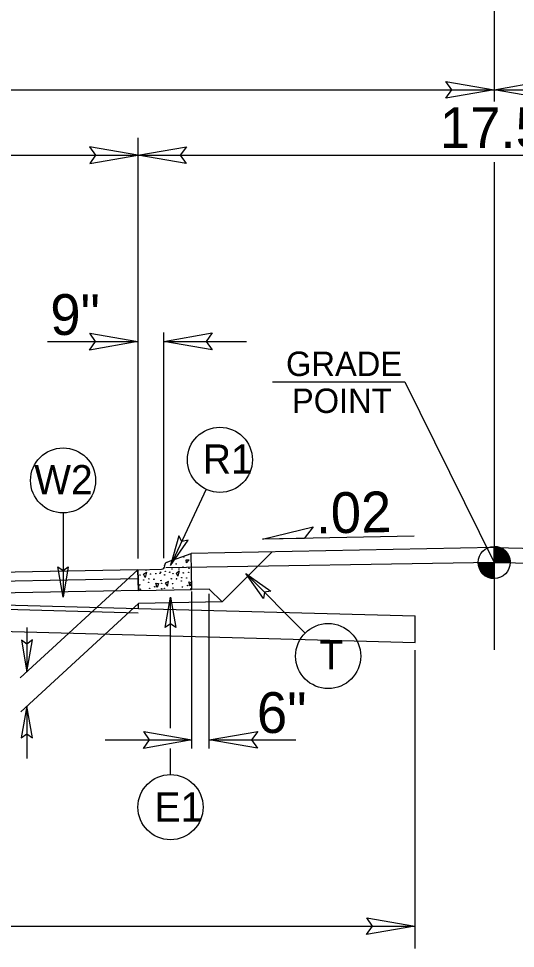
# Model space of a CAD drawing. Extents: x 957297 to 961629, y 830661 to 840840.
# Drawn here: x 959403.5 to 959498.6, y 836659.8 to 836837.7 of the extents above; entities that cross this region are included whole.
import ezdxf

# ---------------------------------------------------------------- set-up
doc = ezdxf.new("R2010")
doc.units = 0
for name, color, linetype in [('Default', 7, 'Continuous'), ('Old_Level_1', 7, 'Continuous'), ('Old_Level_11', 7, 'Continuous'), ('Old_Level_3', 7, 'Continuous'), ('Prop CMT Pvmt Milling', 7, 'Continuous'), ('Prop Dimension Text', 7, 'Continuous'), ('Typical ID Circle CELL', 7, 'Continuous'), ('Typical Terminator CELL', 7, 'Continuous'), ('Typical Text Grade Point CELL', 7, 'Continuous'), ('Typical Text ID Circle CELL', 7, 'Continuous')]:
    doc.layers.add(name, color=color, linetype=linetype)

msp = doc.modelspace()

# ---------------------------------------------------------------- linework, layer by layer
at = {"layer": 'Default'}
for p, q in [((959494.54, 836870.09), (959494.54, 836821.89)), ((959494.54, 836836.14), (959494.54, 836821.89)), ((959494.54, 836810.24), (959494.54, 836716.94)), ((959494.54, 836736.5), (959436.57, 836735.34)), ((959442.47, 836726.12), (959451.99, 836735.65)), ((959494.54, 836736.5), (959552.51, 836735.34)), ((959494.54, 836733.65), (959431.7, 836732.6)), ((959494.54, 836733.65), (959557.49, 836732.39))]:
    msp.add_line(p, q, dxfattribs=at)
at = {"layer": 'Old_Level_1'}
for p, q in [((959239.42, 836824.11), (959494.54, 836824.11)), ((959494.54, 836824.11), (959749.66, 836824.11)), ((959426.38, 836814.92), (959426.38, 836734.43)), ((959332.9, 836811.56), (959426.38, 836811.56)), ((959426.38, 836811.56), (959562.7, 836811.56)), ((959431.33, 836734.45), (959431.33, 836777.67)), ((959409.07, 836775.93), (959426.38, 836775.93)), ((959431.33, 836775.93), (959447.12, 836775.93)), ((959479.24, 836738.66), (959450.18, 836738.08)), ((959494.54, 836733.65), (959494.54, 836736.72)), ((959494.54, 836733.65), (959494.54, 836736.72)), ((959494.54, 836733.65), (959494.54, 836736.72)), ((959491.48, 836733.65), (959494.54, 836733.65)), ((959491.48, 836733.65), (959494.54, 836733.65)), ((959491.48, 836733.65), (959494.54, 836733.65)), ((959497.6, 836733.65), (959494.54, 836733.65)), ((959494.54, 836730.61), (959494.54, 836733.65)), ((959494.54, 836733.65), (959494.54, 836730.61)), ((959497.6, 836733.65), (959494.54, 836733.65)), ((959494.54, 836730.61), (959494.54, 836733.65)), ((959494.54, 836733.65), (959494.54, 836730.61)), ((959497.6, 836733.65), (959494.54, 836733.65)), ((959494.54, 836730.61), (959494.54, 836733.65)), ((959494.54, 836733.65), (959494.54, 836730.61)), ((959426.38, 836732.27), (959206.42, 836727.83)), ((959426.38, 836732.27), (959403.87, 836711.56)), ((959426.42, 836730.55), (959206.42, 836726.1)), ((959419.77, 836728.16), (959354.01, 836726.83)), ((959426.46, 836728.3), (959419.77, 836728.16)), ((959440.02, 836728.57), (959436.72, 836728.5)), ((959440.02, 836728.57), (959442.47, 836726.12)), ((959436.72, 836698.06), (959436.72, 836728.07)), ((959440.02, 836698.06), (959440.02, 836727.68)), ((959426.46, 836725.8), (959403.96, 836705.08)), ((959442.47, 836726.12), (959426.46, 836725.8)), ((959426.46, 836724.85), (959426.46, 836725.8)), ((959479.43, 836718.37), (959479.42, 836723.41)), ((959405.14, 836721.23), (959405.13, 836712.72)), ((959479.39, 836716.88), (959479.39, 836659.8)), ((959405.14, 836706.18), (959405.14, 836696.13)), ((959420.12, 836699.7), (959436.72, 836699.7)), ((959440.02, 836699.7), (959456.62, 836699.7)), ((959133.56, 836664.09), (959479.39, 836664.09))]:
    msp.add_line(p, q, dxfattribs=at)
for points in [[(959494.58, 836736.72), (959494.58, 836736.72), (959494.58, 836733.65)], [(959494.58, 836736.72), (959494.58, 836736.72), (959494.58, 836733.65)], [(959494.58, 836736.72), (959494.58, 836736.72), (959494.58, 836733.65)], [(959494.63, 836736.72), (959494.63, 836733.65)], [(959494.63, 836736.72), (959494.63, 836733.65)], [(959494.63, 836736.72), (959494.63, 836733.65)], [(959494.69, 836736.71), (959494.69, 836733.65)], [(959494.69, 836736.71), (959494.69, 836733.65)], [(959494.69, 836736.71), (959494.69, 836733.65)], [(959494.76, 836736.71), (959494.76, 836733.65)], [(959494.76, 836736.71), (959494.76, 836733.65)], [(959494.76, 836736.71), (959494.76, 836733.65)], [(959494.82, 836736.71), (959494.82, 836733.65)], [(959494.82, 836736.71), (959494.82, 836733.65)], [(959494.82, 836736.71), (959494.82, 836733.65)], [(959494.88, 836736.71), (959494.88, 836733.65)], [(959494.88, 836736.71), (959494.88, 836733.65)], [(959494.88, 836736.71), (959494.88, 836733.65)], [(959494.94, 836736.69), (959494.94, 836733.65)], [(959494.94, 836736.69), (959494.94, 836733.65)], [(959494.94, 836736.69), (959494.94, 836733.65)], [(959495, 836736.69), (959495, 836733.65)], [(959495, 836736.69), (959495, 836733.65)], [(959495, 836736.69), (959495, 836733.65)], [(959495.06, 836736.67), (959495.06, 836733.65)], [(959495.06, 836736.67), (959495.06, 836733.65)], [(959495.06, 836736.67), (959495.06, 836733.65)], [(959495.12, 836736.67), (959495.12, 836733.65)], [(959495.12, 836736.67), (959495.12, 836733.65)], [(959495.12, 836736.67), (959495.12, 836733.65)], [(959495.19, 836736.65), (959495.19, 836733.65)], [(959495.19, 836736.65), (959495.19, 836733.65)], [(959495.19, 836736.65), (959495.19, 836733.65)], [(959495.25, 836736.64), (959495.25, 836733.65)], [(959495.25, 836736.64), (959495.25, 836733.65)], [(959495.25, 836736.64), (959495.25, 836733.65)], [(959495.31, 836736.62), (959495.31, 836733.65)], [(959495.31, 836736.62), (959495.31, 836733.65)], [(959495.31, 836736.62), (959495.31, 836733.65)], [(959495.37, 836736.6), (959495.37, 836733.65)], [(959495.37, 836736.6), (959495.37, 836733.65)], [(959495.37, 836736.6), (959495.37, 836733.65)], [(959495.44, 836736.59), (959495.44, 836733.65)], [(959495.44, 836736.59), (959495.44, 836733.65)], [(959495.44, 836736.59), (959495.44, 836733.65)], [(959495.49, 836736.56), (959495.49, 836733.65)], [(959495.49, 836736.56), (959495.49, 836733.65)], [(959495.49, 836736.56), (959495.49, 836733.65)], [(959495.56, 836736.55), (959495.55, 836733.65)], [(959495.56, 836736.55), (959495.55, 836733.65)], [(959495.56, 836736.55), (959495.55, 836733.65)], [(959495.61, 836736.52), (959495.61, 836733.65)], [(959495.61, 836736.52), (959495.61, 836733.65)], [(959495.61, 836736.52), (959495.61, 836733.65)], [(959495.67, 836736.51), (959495.67, 836733.65)], [(959495.67, 836736.51), (959495.67, 836733.65)], [(959495.67, 836736.51), (959495.67, 836733.65)], [(959495.74, 836736.48), (959495.74, 836733.65)], [(959495.74, 836736.48), (959495.74, 836733.65)], [(959495.74, 836736.48), (959495.74, 836733.65)], [(959495.8, 836736.46), (959495.8, 836733.65)], [(959495.8, 836736.46), (959495.8, 836733.65)], [(959495.8, 836736.46), (959495.8, 836733.65)], [(959495.86, 836736.42), (959495.86, 836733.65)], [(959495.86, 836736.42), (959495.86, 836733.65)], [(959495.86, 836736.42), (959495.86, 836733.65)], [(959495.91, 836736.4), (959495.91, 836733.65)], [(959495.91, 836736.4), (959495.91, 836733.65)], [(959495.91, 836736.4), (959495.91, 836733.65)], [(959495.97, 836736.37), (959495.97, 836733.65)], [(959495.97, 836736.37), (959495.97, 836733.65)], [(959495.97, 836736.37), (959495.97, 836733.65)], [(959496.04, 836736.33), (959496.04, 836733.65)], [(959496.04, 836736.33), (959496.04, 836733.65)], [(959496.04, 836736.33), (959496.04, 836733.65)], [(959496.1, 836736.3), (959496.1, 836733.65)], [(959496.1, 836736.3), (959496.1, 836733.65)], [(959496.1, 836736.3), (959496.1, 836733.65)], [(959496.16, 836736.26), (959496.16, 836733.65)], [(959496.16, 836736.26), (959496.16, 836733.65)], [(959496.16, 836736.26), (959496.16, 836733.65)], [(959496.23, 836736.21), (959496.23, 836733.65)], [(959496.23, 836736.21), (959496.23, 836733.65)], [(959496.23, 836736.21), (959496.23, 836733.65)], [(959496.29, 836736.17), (959496.29, 836733.65)], [(959496.29, 836736.17), (959496.29, 836733.65)], [(959496.29, 836736.17), (959496.29, 836733.65)], [(959496.34, 836736.14), (959496.34, 836733.65)], [(959496.34, 836736.14), (959496.34, 836733.65)], [(959496.34, 836736.14), (959496.34, 836733.65)], [(959496.41, 836736.08), (959496.41, 836733.65)], [(959496.41, 836736.08), (959496.41, 836733.65)], [(959496.41, 836736.08), (959496.41, 836733.65)], [(959496.47, 836736.04), (959496.47, 836733.65)], [(959496.47, 836736.04), (959496.47, 836733.65)], [(959496.47, 836736.04), (959496.47, 836733.65)], [(959496.53, 836735.99), (959496.53, 836733.65)], [(959496.53, 836735.99), (959496.53, 836733.65)], [(959496.53, 836735.99), (959496.53, 836733.65)], [(959496.59, 836735.93), (959496.59, 836733.65)], [(959496.59, 836735.93), (959496.59, 836733.65)], [(959496.59, 836735.93), (959496.59, 836733.65)], [(959496.65, 836735.87), (959496.65, 836733.65)], [(959496.65, 836735.87), (959496.65, 836733.65)], [(959496.65, 836735.87), (959496.65, 836733.65)], [(959496.72, 836735.81), (959496.72, 836733.65)], [(959496.72, 836735.81), (959496.72, 836733.65)], [(959496.72, 836735.81), (959496.72, 836733.65)], [(959496.77, 836735.75), (959496.77, 836733.65)], [(959496.77, 836735.75), (959496.77, 836733.65)], [(959496.77, 836735.75), (959496.77, 836733.65)], [(959496.83, 836735.69), (959496.83, 836733.65)], [(959496.83, 836735.69), (959496.83, 836733.65)], [(959496.83, 836735.69), (959496.83, 836733.65)], [(959496.89, 836735.62), (959496.89, 836733.65)], [(959496.89, 836735.62), (959496.89, 836733.65)], [(959496.89, 836735.62), (959496.89, 836733.65)], [(959496.95, 836735.53), (959496.95, 836733.65)], [(959496.95, 836735.53), (959496.95, 836733.65)], [(959496.95, 836735.53), (959496.95, 836733.65)], [(959497.02, 836735.45), (959497.02, 836733.65)], [(959497.02, 836735.45), (959497.02, 836733.65)], [(959497.02, 836735.45), (959497.02, 836733.65)], [(959497.08, 836735.37), (959497.08, 836733.65)], [(959497.08, 836735.37), (959497.08, 836733.65)], [(959497.08, 836735.37), (959497.08, 836733.65)], [(959497.14, 836735.28), (959497.14, 836733.65)], [(959497.14, 836735.28), (959497.14, 836733.65)], [(959497.14, 836735.28), (959497.14, 836733.65)], [(959491.5, 836733.65), (959491.5, 836733.33)], [(959491.5, 836733.65), (959491.5, 836733.33)], [(959491.5, 836733.65), (959491.5, 836733.33)], [(959491.56, 836733.65), (959491.56, 836732.97)], [(959491.56, 836733.65), (959491.56, 836732.97)], [(959491.56, 836733.65), (959491.56, 836732.97)], [(959491.62, 836733.65), (959491.62, 836732.75)], [(959491.62, 836733.65), (959491.62, 836732.75)], [(959491.62, 836733.65), (959491.62, 836732.75)], [(959491.68, 836733.65), (959491.68, 836732.57)], [(959491.68, 836733.65), (959491.68, 836732.57)], [(959491.68, 836733.65), (959491.68, 836732.57)], [(959491.75, 836733.65), (959491.75, 836732.42)], [(959491.75, 836733.65), (959491.75, 836732.42)], [(959491.75, 836733.65), (959491.75, 836732.42)], [(959491.81, 836733.65), (959491.81, 836732.29)], [(959491.81, 836733.65), (959491.81, 836732.29)], [(959491.81, 836733.65), (959491.81, 836732.29)], [(959491.87, 836733.65), (959491.87, 836732.18)], [(959491.87, 836733.65), (959491.87, 836732.18)], [(959491.87, 836733.65), (959491.87, 836732.18)], [(959491.93, 836733.65), (959491.93, 836732.07)], [(959491.93, 836733.65), (959491.93, 836732.07)], [(959491.93, 836733.65), (959491.93, 836732.07)], [(959492, 836733.65), (959492, 836731.98)], [(959492, 836733.65), (959492, 836731.98)], [(959492, 836733.65), (959492, 836731.98)], [(959492.06, 836733.65), (959492.06, 836731.89)], [(959492.06, 836733.65), (959492.06, 836731.89)], [(959492.06, 836733.65), (959492.06, 836731.89)], [(959492.12, 836733.65), (959492.12, 836731.8)], [(959492.12, 836733.65), (959492.12, 836731.8)], [(959492.12, 836733.65), (959492.12, 836731.8)], [(959492.18, 836733.65), (959492.18, 836731.73)], [(959492.18, 836733.65), (959492.18, 836731.73)], [(959492.18, 836733.65), (959492.18, 836731.73)], [(959492.24, 836733.65), (959492.24, 836731.66)], [(959492.24, 836733.65), (959492.24, 836731.66)], [(959492.24, 836733.65), (959492.24, 836731.66)], [(959492.29, 836733.65), (959492.29, 836731.59)], [(959492.29, 836733.65), (959492.29, 836731.59)], [(959492.29, 836733.65), (959492.29, 836731.59)], [(959492.35, 836733.65), (959492.35, 836731.52)], [(959492.35, 836733.65), (959492.35, 836731.52)], [(959492.35, 836733.65), (959492.35, 836731.52)], [(959492.42, 836733.65), (959492.42, 836731.47)], [(959492.42, 836733.65), (959492.42, 836731.47)], [(959492.42, 836733.65), (959492.42, 836731.47)], [(959492.48, 836733.65), (959492.48, 836731.41)], [(959492.48, 836733.65), (959492.48, 836731.41)], [(959492.48, 836733.65), (959492.48, 836731.41)], [(959492.54, 836733.65), (959492.54, 836731.35)], [(959492.54, 836733.65), (959492.54, 836731.35)], [(959492.54, 836733.65), (959492.54, 836731.35)], [(959492.6, 836733.65), (959492.6, 836731.31)], [(959492.6, 836733.65), (959492.6, 836731.31)], [(959492.6, 836733.65), (959492.6, 836731.31)], [(959492.67, 836733.65), (959492.67, 836731.25)], [(959492.67, 836733.65), (959492.67, 836731.25)], [(959492.67, 836733.65), (959492.67, 836731.25)], [(959492.72, 836733.65), (959492.72, 836731.21)], [(959492.72, 836733.65), (959492.72, 836731.21)], [(959492.72, 836733.65), (959492.72, 836731.21)], [(959492.79, 836733.65), (959492.79, 836731.16)], [(959492.79, 836733.65), (959492.79, 836731.16)], [(959492.79, 836733.65), (959492.79, 836731.16)], [(959492.85, 836733.65), (959492.85, 836731.12)], [(959492.85, 836733.65), (959492.85, 836731.12)], [(959492.85, 836733.65), (959492.85, 836731.12)], [(959492.91, 836733.65), (959492.91, 836731.07)], [(959492.91, 836733.65), (959492.91, 836731.07)], [(959492.91, 836733.65), (959492.91, 836731.07)], [(959492.98, 836733.65), (959492.98, 836731.03)], [(959492.98, 836733.65), (959492.98, 836731.03)], [(959492.98, 836733.65), (959492.98, 836731.03)], [(959493.04, 836733.65), (959493.04, 836731)], [(959493.04, 836733.65), (959493.04, 836731)], [(959493.04, 836733.65), (959493.04, 836731)], [(959493.1, 836733.65), (959493.1, 836730.96)], [(959493.1, 836733.65), (959493.1, 836730.96)], [(959493.1, 836733.65), (959493.1, 836730.96)], [(959493.15, 836733.65), (959493.15, 836730.95)], [(959493.15, 836733.65), (959493.15, 836730.95)], [(959493.15, 836733.65), (959493.15, 836730.95)], [(959493.21, 836733.65), (959493.21, 836730.91)], [(959493.21, 836733.65), (959493.21, 836730.91)], [(959493.21, 836733.65), (959493.21, 836730.91)], [(959493.28, 836733.65), (959493.28, 836730.87)], [(959493.28, 836733.65), (959493.28, 836730.87)], [(959493.28, 836733.65), (959493.28, 836730.87)], [(959493.34, 836733.65), (959493.34, 836730.86)], [(959493.34, 836733.65), (959493.34, 836730.86)], [(959493.34, 836733.65), (959493.34, 836730.86)], [(959493.4, 836733.65), (959493.4, 836730.82)], [(959493.4, 836733.65), (959493.4, 836730.82)], [(959493.4, 836733.65), (959493.4, 836730.82)], [(959493.46, 836733.65), (959493.46, 836730.81)], [(959493.46, 836733.65), (959493.46, 836730.81)], [(959493.46, 836733.65), (959493.46, 836730.81)], [(959493.52, 836733.65), (959493.52, 836730.78)], [(959493.52, 836733.65), (959493.52, 836730.78)], [(959493.52, 836733.65), (959493.52, 836730.78)], [(959493.58, 836733.65), (959493.58, 836730.76)], [(959493.58, 836733.65), (959493.58, 836730.76)], [(959493.58, 836733.65), (959493.58, 836730.76)], [(959493.64, 836733.65), (959493.64, 836730.74)], [(959493.64, 836733.65), (959493.64, 836730.74)], [(959493.64, 836733.65), (959493.64, 836730.74)], [(959493.7, 836733.65), (959493.7, 836730.72)], [(959493.7, 836733.65), (959493.7, 836730.72)], [(959493.7, 836733.65), (959493.7, 836730.72)], [(959493.76, 836733.65), (959493.76, 836730.71)], [(959493.76, 836733.65), (959493.76, 836730.71)], [(959493.76, 836733.65), (959493.76, 836730.71)], [(959493.83, 836733.65), (959493.83, 836730.7)], [(959493.83, 836733.65), (959493.83, 836730.7)], [(959493.83, 836733.65), (959493.83, 836730.7)], [(959493.89, 836733.65), (959493.89, 836730.68)], [(959493.89, 836733.65), (959493.89, 836730.68)], [(959493.89, 836733.65), (959493.89, 836730.68)], [(959493.95, 836733.65), (959493.95, 836730.66)], [(959493.95, 836733.65), (959493.95, 836730.66)], [(959493.95, 836733.65), (959493.95, 836730.66)], [(959494.01, 836733.65), (959494.01, 836730.66)], [(959494.01, 836733.65), (959494.01, 836730.66)], [(959494.01, 836733.65), (959494.01, 836730.66)], [(959494.07, 836733.65), (959494.07, 836730.65)], [(959494.07, 836733.65), (959494.07, 836730.65)], [(959494.07, 836733.65), (959494.07, 836730.65)], [(959494.13, 836733.65), (959494.13, 836730.62)], [(959494.13, 836733.65), (959494.13, 836730.62)], [(959494.13, 836733.65), (959494.13, 836730.62)], [(959494.2, 836733.65), (959494.2, 836730.62)], [(959494.2, 836733.65), (959494.2, 836730.62)], [(959494.2, 836733.65), (959494.2, 836730.62)], [(959494.26, 836733.65), (959494.26, 836730.62)], [(959494.26, 836733.65), (959494.26, 836730.62)], [(959494.26, 836733.65), (959494.26, 836730.62)], [(959494.32, 836733.65), (959494.32, 836730.61)], [(959494.32, 836733.65), (959494.32, 836730.61)], [(959494.32, 836733.65), (959494.32, 836730.61)], [(959494.38, 836733.65), (959494.38, 836730.61)], [(959494.38, 836733.65), (959494.38, 836730.61)], [(959494.38, 836733.65), (959494.38, 836730.61)], [(959494.43, 836733.65), (959494.43, 836730.61)], [(959494.43, 836733.65), (959494.43, 836730.61)], [(959494.43, 836733.65), (959494.43, 836730.61)], [(959494.49, 836733.65), (959494.49, 836730.61), (959494.49, 836730.61)], [(959494.49, 836733.65), (959494.49, 836730.61), (959494.49, 836730.61)], [(959494.49, 836733.65), (959494.49, 836730.61), (959494.49, 836730.61)], [(959497.2, 836735.17), (959497.2, 836733.65)], [(959497.2, 836735.17), (959497.2, 836733.65)], [(959497.2, 836735.17), (959497.2, 836733.65)], [(959497.26, 836735.07), (959497.26, 836733.65)], [(959497.26, 836735.07), (959497.26, 836733.65)], [(959497.26, 836735.07), (959497.26, 836733.65)], [(959497.32, 836734.92), (959497.32, 836733.65)], [(959497.32, 836734.92), (959497.32, 836733.65)], [(959497.32, 836734.92), (959497.32, 836733.65)], [(959497.39, 836734.78), (959497.39, 836733.65)], [(959497.39, 836734.78), (959497.39, 836733.65)], [(959497.39, 836734.78), (959497.39, 836733.65)], [(959497.45, 836734.62), (959497.45, 836733.65)], [(959497.45, 836734.62), (959497.45, 836733.65)], [(959497.45, 836734.62), (959497.45, 836733.65)], [(959497.51, 836734.41), (959497.51, 836733.65)], [(959497.51, 836734.41), (959497.51, 836733.65)], [(959497.51, 836734.41), (959497.51, 836733.65)], [(959497.57, 836734.1), (959497.57, 836733.65)], [(959497.57, 836734.1), (959497.57, 836733.65)], [(959497.57, 836734.1), (959497.57, 836733.65)], [(959426.46, 836724.85), (959479.42, 836723.41)], [(959306.49, 836723.08), (959479.42, 836718.37)]]:
    msp.add_lwpolyline(points, dxfattribs=at)
msp.add_circle((959494.54, 836733.66), 3.06, dxfattribs=at)
msp.add_circle((959494.54, 836733.66), 3.06, dxfattribs=at)
msp.add_circle((959494.54, 836733.66), 3.06, dxfattribs=at)
for start, end in [(359.9905, 89.9905), (359.9905, 89.9905), (359.9905, 89.9905), (179.9905, 269.9905), (179.9905, 269.9905), (179.9905, 269.9905)]:
    msp.add_arc((959494.54, 836733.66), 3.06, start, end, dxfattribs=at)
at = {"layer": 'Old_Level_11'}
for p, q in [((959450.18, 836738.08), (959459.93, 836740.5)), ((959459.93, 836740.5), (959458.2, 836738.24)), ((959458.2, 836738.24), (959450.18, 836738.08))]:
    msp.add_line(p, q, dxfattribs=at)
at = {"layer": 'Old_Level_3'}
for p, q in [((959431.92, 836733.68), (959436.57, 836735.34)), ((959436.72, 836728.5), (959436.57, 836735.34)), ((959435.59, 836734.14), (959436.18, 836734.16)), ((959435.64, 836733.56), (959435.59, 836734.14)), ((959436.18, 836734.16), (959435.64, 836733.56)), ((959426.38, 836732.27), (959430.87, 836732.37)), ((959426.38, 836732.27), (959426.46, 836728.29)), ((959426.46, 836728.29), (959426.38, 836732.23)), ((959427.45, 836731.39), (959428, 836731.81)), ((959428, 836731.81), (959427.74, 836730.78)), ((959431.49, 836733.02), (959431.49, 836733.06)), ((959433.73, 836731.63), (959434.28, 836732.05)), ((959434.28, 836732.05), (959434.02, 836731.02)), ((959427.74, 836730.78), (959427.45, 836731.39)), ((959432.22, 836730.03), (959431.61, 836729.68)), ((959432.02, 836729.13), (959432.22, 836730.03)), ((959434.02, 836731.02), (959433.73, 836731.63)), ((959436.09, 836729.93), (959436.58, 836729.84)), ((959436.35, 836729.09), (959436.09, 836729.93)), ((959426.46, 836728.29), (959436.72, 836728.5)), ((959429.81, 836729.68), (959430.3, 836729.6)), ((959430.07, 836728.85), (959429.81, 836729.68)), ((959430.3, 836729.6), (959430.07, 836728.85)), ((959431.61, 836729.68), (959432.02, 836729.13)), ((959436.58, 836729.84), (959436.35, 836729.09))]:
    msp.add_line(p, q, dxfattribs=at)
for centre in [(959432.76, 836733.53), (959433.69, 836733.39), (959435.15, 836734.72), (959427.93, 836732.18), (959430.7, 836731.79), (959431.62, 836731.96), (959432.46, 836731.79), (959432.91, 836732.42), (959434.21, 836732.42), (959435, 836732.77), (959435.06, 836731.66), (959436.08, 836731.78), (959436.12, 836732.52), (959426.48, 836730.29), (959426.8, 836731.26), (959427.47, 836730.28), (959428.41, 836729.87), (959428.49, 836730.52), (959428.78, 836731.42), (959429.42, 836730.45), (959429.8, 836731.54), (959430.6, 836731.58), (959430.78, 836730.2), (959431.48, 836731.28), (959432.77, 836730.53), (959433.09, 836731.5), (959433.75, 836730.52), (959434.69, 836730.11), (959434.77, 836730.76), (959435.7, 836730.69), (959426.72, 836729.37), (959426.83, 836728.54), (959428.62, 836728.7), (959429.6, 836729), (959430.9, 836729.66), (959430.92, 836728.61), (959431.44, 836728.71), (959433, 836729.61), (959433.11, 836728.78), (959434.9, 836728.94), (959435.88, 836729.24)]:
    msp.add_circle(centre, 0.0434, dxfattribs=at)
for centre, radius, start, end in [((959432.13, 836733.07), 0.641, 109.641, 181.206), ((959430.85, 836733.01), 0.641, 271.206, 1.206), ((959436.48, 836728.54), 0.0434, 26.9645, 154.1675)]:
    msp.add_arc(centre, radius, start, end, dxfattribs=at)
at = {"layer": 'Prop CMT Pvmt Milling'}
for points in [[(959306.49, 836728.12), (959426.46, 836724.85)], [(959426.44, 836723.98), (959306.51, 836727.25)]]:
    msp.add_lwpolyline(points, dxfattribs=at)
at = {"layer": 'Typical ID Circle CELL'}
for p, q in [((959439.43, 836747.66), (959432.63, 836733.08)), ((959412.05, 836743.13), (959412.05, 836727.04)), ((959458.38, 836720.15), (959447, 836731.53)), ((959432.6, 836701.97), (959432.6, 836726.99)), ((959432.6, 836693.05), (959432.6, 836698.04))]:
    msp.add_line(p, q, dxfattribs=at)
for centre in [(959442.06, 836753.3), (959412.05, 836749.35), (959462.78, 836715.75), (959432.6, 836686.83)]:
    msp.add_circle(centre, 6.23, dxfattribs=at)
at = {"layer": 'Typical Terminator CELL'}
for points in [[(959485.32, 836825.69), (959494.54, 836824.11), (959485.27, 836822.47), (959486.44, 836824.11)], [(959503.76, 836822.52), (959494.54, 836824.11), (959503.81, 836825.74), (959502.63, 836824.11)], [(959417.15, 836809.98), (959426.38, 836811.56), (959417.1, 836813.2), (959418.28, 836811.56)], [(959435.6, 836809.98), (959426.38, 836811.56), (959435.65, 836813.2), (959434.47, 836811.56)], [(959417.15, 836777.52), (959426.38, 836775.93), (959417.1, 836774.29), (959418.28, 836775.93)], [(959440.55, 836774.34), (959431.33, 836775.93), (959440.6, 836777.57), (959439.43, 836775.93)], [(959434.17, 836738.72), (959432.63, 836733.08), (959436.01, 836737.9), (959434.77, 836737.66)], [(959413.04, 836732.8), (959412.05, 836727.04), (959411.02, 836732.84), (959412.05, 836732.1)], [(959450.38, 836726.75), (959447, 836731.53), (959451.83, 836728.15), (959450.58, 836727.95)], [(959431.61, 836721.23), (959432.6, 836726.99), (959433.63, 836721.2), (959432.6, 836721.93)], [(959404.09, 836718.79), (959405.13, 836712.72), (959406.21, 836718.83), (959405.14, 836718.05)], [(959406.19, 836700.11), (959405.14, 836706.18), (959404.06, 836700.08), (959405.14, 836700.85)], [(959427.5, 836701.29), (959436.72, 836699.7), (959427.44, 836698.06), (959428.62, 836699.7)], [(959449.24, 836698.11), (959440.02, 836699.7), (959449.29, 836701.34), (959448.11, 836699.7)], [(959470.16, 836665.67), (959479.39, 836664.09), (959470.11, 836662.45), (959471.29, 836664.09)]]:
    msp.add_lwpolyline(points, close=True, dxfattribs=at)
at = {"layer": 'Typical Text Grade Point CELL'}
for p, q in [((959452.1, 836768.22), (959477.43, 836768.22)), ((959452.1, 836768.21), (959477.43, 836768.21)), ((959477.43, 836768.21), (959494.54, 836733.65)), ((959477.43, 836768.21), (959494.54, 836733.65))]:
    msp.add_line(p, q, dxfattribs=at)

# ---------------------------------------------------------------- texts
at = {"layer": 'Old_Level_11'}
for s, p in [('GRADE', (959454.71, 836769.33)), ('POINT', (959455.84, 836762.26))]:
    msp.add_text(s, height=4.671, dxfattribs=at).set_placement(p)
at = {"layer": 'Prop Dimension Text'}
for s, rotation, p in [("17.5'", 0, (959484.14, 836812.94)), ('9"', 0, (959409.6, 836777.19)), ('.02', 1.1839, (959460.45, 836739.18)), ('6"', 0, (959449.14, 836701.03))]:
    msp.add_text(s, height=7.801, rotation=rotation, dxfattribs=at).set_placement(p)
at = {"layer": 'Typical Text ID Circle CELL'}
for s, height, p in [('R1', 5.572, (959438.81, 836750.67)), ('W2', 5.572, (959406.53, 836746.72)), ('T', 5.57, (959461.1, 836713.18)), ('E1', 5.572, (959429.57, 836684.08))]:
    msp.add_text(s, height=height, dxfattribs=at).set_placement(p)

doc.saveas('drawing.dxf')
